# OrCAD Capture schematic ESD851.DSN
size A; title: ESD851 36V Bidirectional ESD Protection Diode in SOD-323; rev: 1.0; note: Datasheet: SLVSHZ9
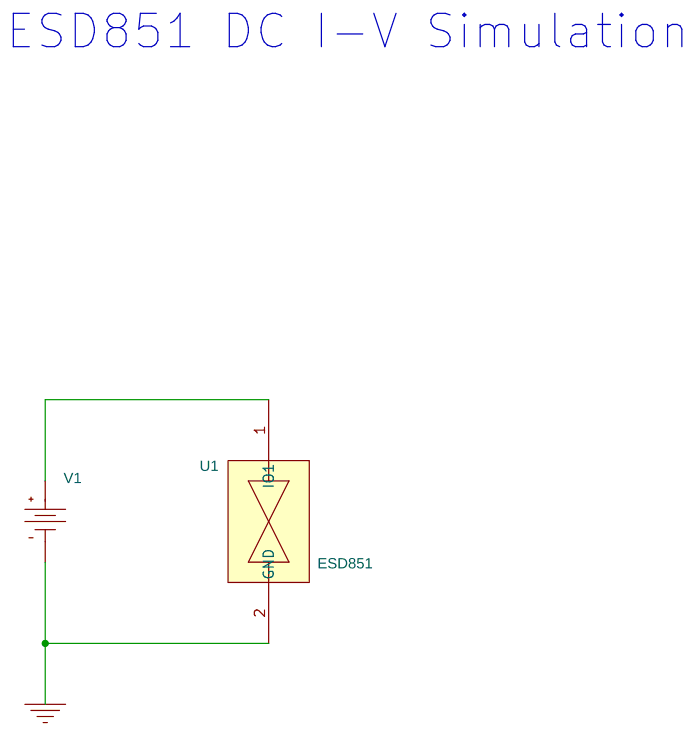
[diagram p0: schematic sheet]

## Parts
U1  ESD851
V1  VDC

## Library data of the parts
U1 = ESD851
V1 = VDC

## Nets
0: U1.2(GND) V1.1(-)
N02865: U1.1(IO1) V1.0(+)

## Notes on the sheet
- ESD851 DC I-V Simulation
